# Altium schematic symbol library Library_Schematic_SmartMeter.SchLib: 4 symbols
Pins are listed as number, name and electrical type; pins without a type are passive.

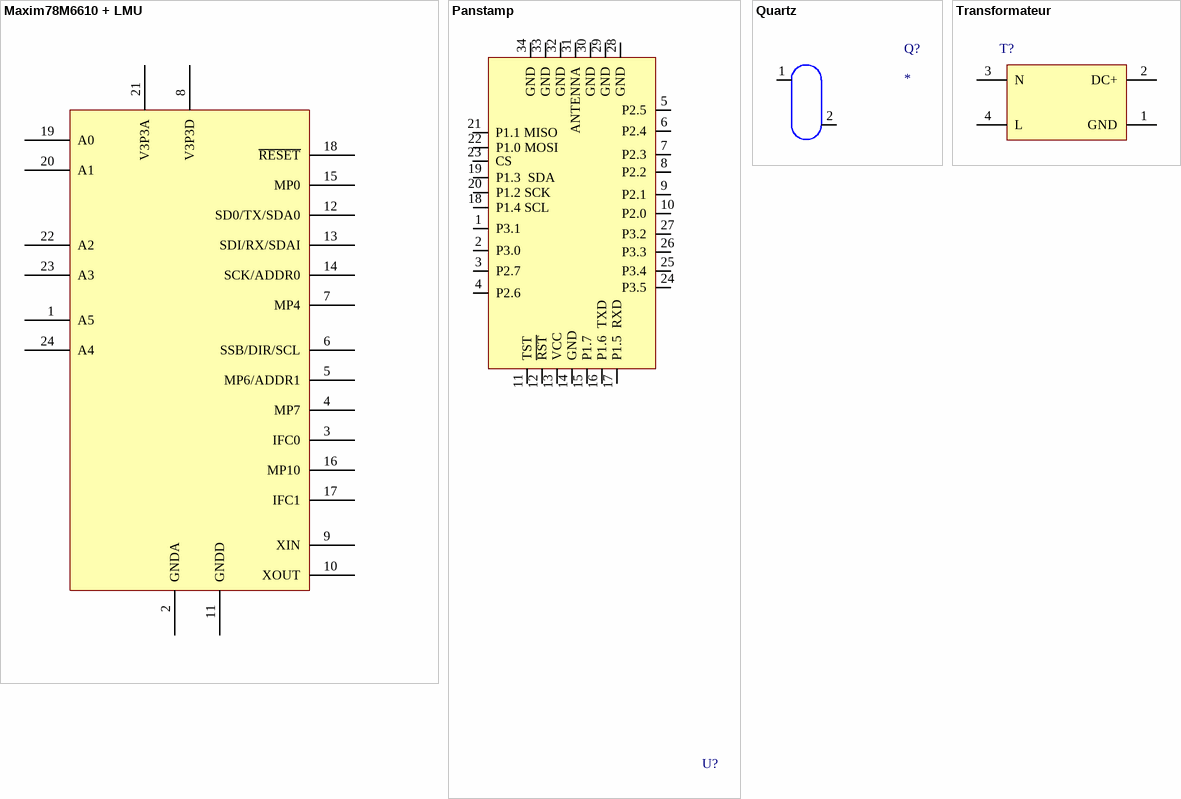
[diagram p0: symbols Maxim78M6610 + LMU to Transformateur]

## Maxim78M6610 + LMU
designator U?, comment Maxim_78M6610+LMU
Mesure d'énergie IC ENERGY MM PROCESSOR 24TQFN; Manufacturer: Maxim Integrated
footprint 21_0139I_T2444_4
pins: 1 A5, 2 GNDA, 3 IFC0, 4 MP7, 5 MP6/ADDR1, 6 SSB/DIR/SCL, 7 MP4, 8 V3P3D, 9 XIN, 10 XOUT, 11 GNDD, 12 SD0/TX/SDA0, 13 SDI/RX/SDAI, 14 SCK/ADDR0, 15 MP0, 16 MP10, 17 IFC1, 18 ~{RESET}, 19 A0, 20 A1, 21 V3P3A, 22 A2, 23 A3, 24 A4

## Panstamp
designator U?  (value not drawn)
Panstamp NRG 2.0
footprint PCBComponent_1
pins: 1 P3.1, 2 P3.0, 3 P2.7, 4 P2.6, 5 P2.5, 6 P2.4, 7 P2.3, 8 P2.2, 9 P2.1, 10 P2.0, 11 TST, 12 ~{RST}, 13 VCC (power), 14 GND (power), 15 P1.7, 16 P1.6  TXD, 17 P1.5  RXD, 18 P1.4 SCL, 19 P1.3  SDA, 20 P1.2 SCK, 21 P1.1 MISO, 22 P1.0 MOSI, 23 CS, 24 P3.5, 25 P3.4, 26 P3.3, 27 P3.2, 28 GND (power), 29 GND (power), 30 GND (power), 31 ANTENNA, 32 GND (power), 33 GND (power), 34 GND (power)

## Quartz
designator Q?
Oscillateur 20 MHz
footprint PCBComponent_1
pins: 1 (power), 2 (power)

## Transformateur
designator T?  (value not drawn)
230V AC to 3.3V DC
footprint PCBComponent_1
pins: 1 GND (power), 2 DC+ (power), 3 N (power), 4 L (power)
